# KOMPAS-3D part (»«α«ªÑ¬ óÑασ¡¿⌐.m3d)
File: created 20.08.2015 19:35:12, last saved 22.07.2016 14:57:03.
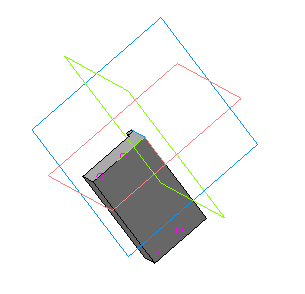
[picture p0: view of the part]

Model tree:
1. Эскиз:1
2. Операция выдавливания:1
     Расстояние 1 = 8
3. Эскиз:2
4. Операция выдавливания:2
     Расстояние 1 = 1
5. Эскиз:3
6. Операция выдавливания:3
     Расстояние 1 = 2.5; Угол 1 = 8
7. Эскиз:4
8. Вырезать элемент выдавливания:1
     Расстояние 1 = 20
9. Эскиз:5
10. Вырезать элемент выдавливания:2
     Расстояние 1 = 3; Угол 1 = 19
11. Скругление:1
     Радиус = 1
12. Скругление:2
     Радиус = 1
13. Скругление:3
     Радиус = 1
14. Эскиз:6
15. Эскиз:7
16. Вырезать элемент выдавливания:3
     Расстояние 1 = 2.5
17. Эскиз:8
18. Вырезать элемент выдавливания:4
     Расстояние 1 = 42
19. Операция выдавливания:4
     Расстояние 1 = 0.8; Расстояние 2 = 1.5
20. Эскиз:9
21. Вырезать элемент выдавливания:5
     Расстояние 1 = 30
22. Эскиз:10
23. Вырезать элемент выдавливания:6
     Расстояние 1 = 10
24. Эскиз:11
25. Операция выдавливания:5
     Расстояние 1 = 3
